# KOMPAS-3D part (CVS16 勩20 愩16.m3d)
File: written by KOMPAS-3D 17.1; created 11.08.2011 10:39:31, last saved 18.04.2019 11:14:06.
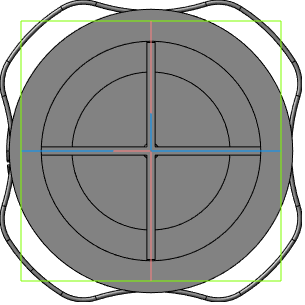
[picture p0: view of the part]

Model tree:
1. Плоскость XY
2. Плоскость ZX
3. Плоскость ZY
4. Ось X
5. Ось Y
6. Ось Z
7. Начало координат
8. Операция без истории:2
